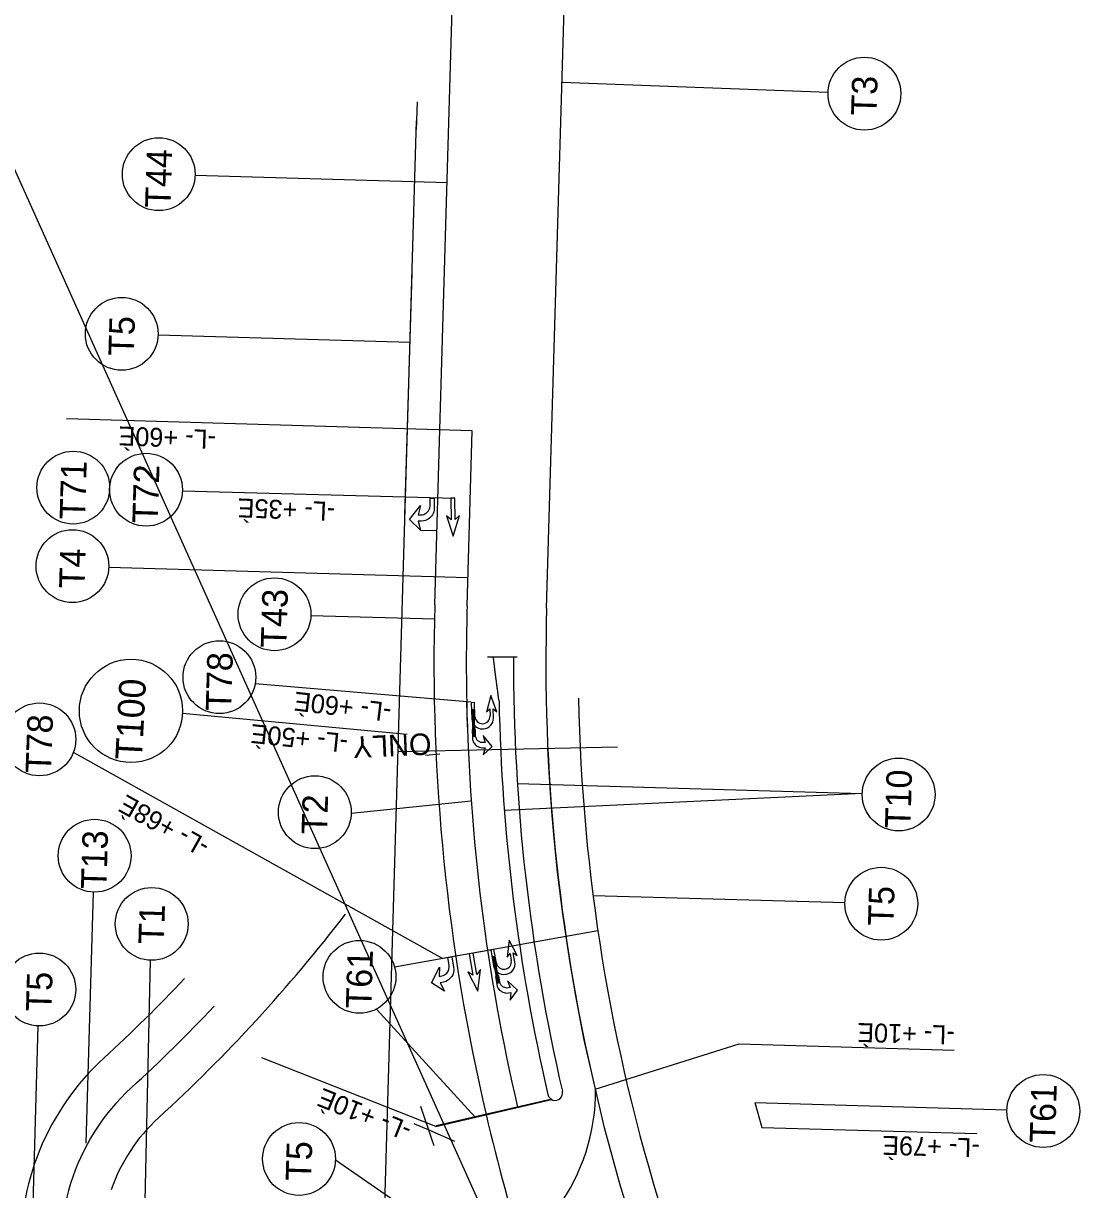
# Model space of a CAD drawing. Extents: x 1657109 to 2100937, y 684916 to 883211.
# Drawn here: x 2097527.1 to 2097918.8, y 685898 to 686330.3 of the extents above; entities that cross this region are included whole.
import ezdxf

# ---------------------------------------------------------------- set-up
doc = ezdxf.new("R2010")
doc.units = 0
for name, color, linetype in [('Prop CMT Detour Removal', 7, 'Continuous'), ('Prop CMT Pvmt Course 1', 7, 'Continuous'), ('Prop CMT Pvmt Gravel', 7, 'Continuous'), ('Prop Conc 1ft 6in Curb and Gutter', 7, 'Continuous'), ('Prop Conc 2ft 6in Curb and Gutter', 7, 'Continuous'), ('Prop Conc Curb 8in x 18in', 7, 'Continuous'), ('Prop Conc Curb and Gutter', 7, 'Continuous'), ('Prop Dimension', 7, 'Continuous'), ('Prop DSN Text', 7, 'Continuous'), ('Prop EOT', 7, 'Continuous'), ('Prop Guardrail Anchor Unit CELL', 7, 'Continuous'), ('Prop Lane Arrow CELL', 7, 'Continuous'), ('Prop Lane Lines', 7, 'Continuous'), ('Prop Paved Shoulder', 7, 'Continuous'), ('Prop Rem of Exist Asph Pvmt', 7, 'Continuous'), ('Prop Sign E Chevron Right', 7, 'Continuous'), ('Scratch_Level_1', 7, 'Continuous'), ('Scratch_Level_3', 7, 'Continuous'), ('Scratch_Level_5', 7, 'Continuous'), ('Sign Bubble', 7, 'Continuous')]:
    doc.layers.add(name, color=color, linetype=linetype)

msp = doc.modelspace()

# ---------------------------------------------------------------- linework, layer by layer
at = {"layer": 'Prop CMT Detour Removal'}
msp.add_line((2097679.67, 686114.82), (2097681.55, 686179.67), dxfattribs=at)
msp.add_arc((2098415.1, 686093.44), 735.75, 178.33483, 193.16901, dxfattribs=at)
at = {"layer": 'Prop CMT Pvmt Course 1'}
for p, q in [((2097700.5, 686081.18), (2097698.81, 686075)), ((2097702.62, 686075.13), (2097700.5, 686081.18)), ((2097694.37, 686078.56), (2097693.17, 686078.51)), ((2097693.17, 686078.51), (2097693.38, 686072.5)), ((2097694.55, 686073.44), (2097694.37, 686078.56)), ((2097698.81, 686075), (2097700.07, 686076.24)), ((2097700.07, 686076.24), (2097700.17, 686073.64)), ((2097701.4, 686072.78), (2097701.28, 686076.29)), ((2097701.28, 686076.29), (2097702.62, 686075.13)), ((2097697.33, 686068.82), (2097697.72, 686068.83)), ((2097707.3, 685990.52), (2097706.5, 685984.16)), ((2097710.25, 685984.83), (2097707.3, 685990.52)), ((2097701.6, 685987.06), (2097700.41, 685986.85)), ((2097700.41, 685986.85), (2097701.47, 685980.92)), ((2097702.5, 685982.02), (2097701.6, 685987.06)), ((2097709.37, 685982.33), (2097708.76, 685985.79)), ((2097708.76, 685985.79), (2097710.25, 685984.83)), ((2097706.5, 685984.16), (2097707.57, 685985.58)), ((2097707.57, 685985.58), (2097708.03, 685983.01)), ((2097705.9, 685977.84), (2097706.29, 685977.91))]:
    msp.add_line(p, q, dxfattribs=at)
for centre, radius, start, end in [((2097697.19, 686072.63), 3.82, 182.0041, 272.0041), ((2097697.36, 686073.54), 2.81, 182.0041, 272.0041), ((2097697.36, 686073.54), 2.81, 272.0041, 2.0041), ((2097697.59, 686072.65), 3.82, 272.0041, 2.0041), ((2097705.26, 685982.52), 2.81, 190.1217, 280.1217), ((2097705.26, 685982.52), 2.81, 280.1217, 10.1217), ((2097705.61, 685981.66), 3.82, 280.1217, 10.1217), ((2097705.23, 685981.59), 3.82, 190.1217, 280.1217)]:
    msp.add_arc(centre, radius, start, end, dxfattribs=at)
at = {"layer": 'Prop CMT Pvmt Gravel'}
for p, q in [((2097825.48, 686304.65), (2097726.81, 686308.43)), ((2097590.82, 686274.01), (2097684.21, 686271.29)), ((2097577.09, 686214.84), (2097670.49, 686212.13)), ((2097693.55, 686179.33), (2097543.06, 686183.7)), ((2097586.09, 686157.06), (2097687.16, 686154.36)), ((2097558.8, 686128.74), (2097691.96, 686124.87)), ((2097633.72, 686110.89), (2097679.53, 686109.56)), ((2097693.16, 686078.66), (2097613.09, 686085.53)), ((2097586.13, 686074.67), (2097669.4, 686066.87)), ((2097710.28, 686048.58), (2097838.17, 686044.86)), ((2097648.7, 686037.52), (2097693.17, 686042.2)), ((2097838.17, 686044.86), (2097705.47, 686038.57)), ((2097550.44, 685915.28), (2097553.14, 686008.3)), ((2097738.34, 686007.11), (2097831.74, 686004.4)), ((2097571.62, 685867.71), (2097574.3, 685983.02)), ((2097694.69, 685924.88), (2097658.05, 685964.97)), ((2097529.26, 685842.85), (2097532.63, 685958.71)), ((2097739.11, 685935.27), (2097792.55, 685952.06)), ((2097792.55, 685952.06), (2097872.25, 685949.75)), ((2097680.01, 685921.44), (2097615.5, 685946.84)), ((2097798.4, 685930.28), (2097891.8, 685927.56)), ((2097800.96, 685921.11), (2097880.66, 685918.8)), ((2097642.82, 685909.02), (2097700.19, 685869.55))]:
    msp.add_line(p, q, dxfattribs=at)
msp.add_lwpolyline([(2097701.6, 685987.06), (2097693.9, 685985.69), (2097682.52, 685983.66), (2097545.68, 686060.1)], dxfattribs=at)
for centre, radius in [((2097838.98, 686304.26), 13.5), ((2097577.32, 686274.4), 13.5), ((2097563.6, 686215.23), 13.5), ((2097545.61, 686158.24), 13.5), ((2097572.6, 686157.45), 13.5), ((2097545.31, 686129.14), 13.5), ((2097620.22, 686111.28), 13.5), ((2097599.81, 686087.96), 13.5), ((2097567.01, 686075.48), 19.14), ((2097533.07, 686064.92), 13.5), ((2097851.66, 686044.47), 13.5), ((2097635.2, 686037.92), 13.5), ((2097553.53, 686021.8), 13.5), ((2097845.23, 686004.01), 13.5), ((2097574.7, 685996.52), 13.5), ((2097651.75, 685976.91), 13.5), ((2097533.02, 685972.21), 13.5), ((2097905.29, 685927.17), 13.5), ((2097629.33, 685909.41), 13.5)]:
    msp.add_circle(centre, radius, dxfattribs=at)
at = {"layer": 'Prop Conc 1ft 6in Curb and Gutter'}
msp.add_arc((2098415.1, 686093.44), 723.75, 181.14892, 193.16901, dxfattribs=at)
at = {"layer": 'Prop Conc 2ft 6in Curb and Gutter'}
msp.add_line((2097691.66, 686114.47), (2097693.55, 686179.33), dxfattribs=at)
for centre, radius, start, end in [((2098415.1, 686093.44), 723.75, 178.33483, 181.14892), ((2097665.53, 685934.68), 73.78, 287.7359, 0.5072)]:
    msp.add_arc(centre, radius, start, end, dxfattribs=at)
at = {"layer": 'Prop Conc Curb 8in x 18in'}
msp.add_lwpolyline([(2097710.24, 686095.39), (2097702.15, 686095.41), (2097699.19, 686095.42)], dxfattribs=at)
at = {"layer": 'Prop Conc Curb and Gutter'}
for centre, radius, start, end in [((2098415.1, 686093.44), 706.25, 179.84144, 193.00645), ((2098415.1, 686093.44), 711.75, 181.14892, 193.00593), ((2097724.29, 685933.87), 2.75, 192.8717, 13.0065)]:
    msp.add_arc(centre, radius, start, end, dxfattribs=at)
msp.add_spline([(2097703.5, 686079.17), (2097703.4, 686079.84), (2097703.31, 686080.51), (2097703.22, 686081.18), (2097703.12, 686081.85), (2097703.03, 686082.52), (2097702.94, 686083.2), (2097702.85, 686083.87), (2097702.76, 686084.54), (2097702.67, 686085.21), (2097702.58, 686085.88), (2097702.5, 686086.56), (2097702.41, 686087.23), (2097702.32, 686087.9), (2097702.24, 686088.58), (2097702.15, 686089.25), (2097702.07, 686089.92), (2097701.98, 686090.6), (2097701.9, 686091.27), (2097701.82, 686091.94), (2097701.73, 686092.62), (2097701.65, 686093.29), (2097701.57, 686093.97), (2097701.49, 686094.64), (2097701.41, 686095.31), (2097701.4, 686095.41)], degree=3, dxfattribs=at)
at = {"layer": 'Prop Dimension'}
for p, q in [((2097674.42, 686142.42), (2097680.47, 686142.33)), ((2097691.75, 686069.43), (2097691.5, 686078.93)), ((2097676.17, 686059.12), (2097681.48, 686059.58)), ((2097740.15, 685993.94), (2097664.77, 685980.49))]:
    msp.add_line(p, q, dxfattribs=at)
at = {"layer": 'Prop DSN Text'}
for points in [[(2097679.45, 685914.25), (2097678.59, 685916.78), (2097674.46, 685928.78)], [(2097671.93, 685922.56), (2097677.42, 685920.16), (2097686.96, 685915.99)]]:
    msp.add_lwpolyline(points, dxfattribs=at)
at = {"layer": 'Prop EOT'}
msp.add_line((2097721.15, 686113.61), (2097743.93, 686897.18), dxfattribs=at)
msp.add_arc((2098415.1, 686093.44), 694.25, 178.33483, 193.16901, dxfattribs=at)
at = {"layer": 'Prop Guardrail Anchor Unit CELL'}
for centre, radius, start, end in [((2097180.74, 686358.34), 587.6, 312.43424, 322.438), ((2097180.74, 686358.34), 557.6, 312.4342, 316.7547), ((2097621.08, 685876.69), 95, 132.4342, 183.1561), ((2097621.08, 685876.69), 65, 132.4342, 160.85)]:
    msp.add_arc(centre, radius, start, end, dxfattribs=at)
at = {"layer": 'Prop Lane Arrow CELL'}
msp.add_line((2097668.62, 686148), (2097671.24, 686237.8), dxfattribs=at)
for radius, start, end in [(682.25, 181.10817, 197.44435), (735.75, 193.16901, 201.91468)]:
    msp.add_arc((2098415.1, 686093.44), radius, start, end, dxfattribs=at)
at = {"layer": 'Prop Lane Lines'}
for p, q in [((2097680.02, 685921.45), (2097722.93, 685931.49)), ((2097798.4, 685930.28), (2097800.96, 685921.11))]:
    msp.add_line(p, q, dxfattribs=at)
at = {"layer": 'Prop Paved Shoulder'}
for points in [[(2097694.73, 686068.6), (2097693.54, 686068.57), (2097693.62, 686065.49), (2097693.66, 686064.93), (2097693.75, 686064.5), (2097693.91, 686064.03), (2097694.12, 686063.65), (2097694.34, 686063.35), (2097694.69, 686062.97), (2097694.99, 686062.71), (2097695.35, 686062.44), (2097695.83, 686062.17), (2097696.21, 686062.03), (2097696.72, 686061.9), (2097697.41, 686061.82), (2097698.37, 686061.84), (2097697.64, 686059.15), (2097700.93, 686062.31), (2097697.66, 686066.39), (2097698.32, 686063.73), (2097697.53, 686063.71), (2097697.08, 686063.72), (2097696.67, 686063.82), (2097696.35, 686063.97), (2097695.93, 686064.2), (2097695.64, 686064.42), (2097695.31, 686064.8), (2097695.08, 686065.24), (2097694.9, 686065.69), (2097694.78, 686066.32)], [(2097694.73, 686068.59), (2097693.54, 686068.56), (2097693.61, 686065.49), (2097693.66, 686064.93), (2097693.75, 686064.5), (2097693.91, 686064.03), (2097694.12, 686063.64), (2097694.34, 686063.35), (2097694.68, 686062.97), (2097694.99, 686062.71), (2097695.35, 686062.44), (2097695.83, 686062.17), (2097696.21, 686062.03), (2097696.72, 686061.89), (2097697.41, 686061.82), (2097698.37, 686061.84), (2097697.64, 686059.15), (2097700.93, 686062.31), (2097697.66, 686066.39), (2097698.32, 686063.73), (2097697.53, 686063.71), (2097697.08, 686063.72), (2097696.67, 686063.82), (2097696.34, 686063.96), (2097695.93, 686064.2), (2097695.64, 686064.41), (2097695.31, 686064.8), (2097695.08, 686065.24), (2097694.9, 686065.69), (2097694.78, 686066.32)], [(2097703.36, 685977.25), (2097702.18, 685977.05), (2097702.69, 685974.02), (2097702.82, 685973.47), (2097702.96, 685973.06), (2097703.19, 685972.62), (2097703.46, 685972.26), (2097703.71, 685972), (2097704.11, 685971.67), (2097704.45, 685971.46), (2097704.85, 685971.25), (2097705.35, 685971.05), (2097705.75, 685970.96), (2097706.27, 685970.9), (2097706.97, 685970.92), (2097707.91, 685971.08), (2097707.58, 685968.31), (2097710.39, 685971.9), (2097706.57, 685975.48), (2097707.6, 685972.94), (2097706.82, 685972.81), (2097706.38, 685972.76), (2097705.95, 685972.8), (2097705.61, 685972.89), (2097705.17, 685973.07), (2097704.85, 685973.24), (2097704.47, 685973.58), (2097704.18, 685973.98), (2097703.93, 685974.4), (2097703.73, 685975)], [(2097703.36, 685977.25), (2097702.18, 685977.05), (2097702.69, 685974.02), (2097702.82, 685973.47), (2097702.96, 685973.06), (2097703.19, 685972.62), (2097703.46, 685972.27), (2097703.71, 685972), (2097704.11, 685971.67), (2097704.45, 685971.46), (2097704.85, 685971.25), (2097705.36, 685971.05), (2097705.75, 685970.96), (2097706.27, 685970.9), (2097706.97, 685970.92), (2097707.91, 685971.08), (2097707.58, 685968.31), (2097710.39, 685971.9), (2097706.57, 685975.48), (2097707.6, 685972.94), (2097706.82, 685972.81), (2097706.38, 685972.76), (2097705.95, 685972.8), (2097705.61, 685972.9), (2097705.17, 685973.07), (2097704.85, 685973.24), (2097704.47, 685973.58), (2097704.18, 685973.98), (2097703.94, 685974.4), (2097703.74, 685975)]]:
    msp.add_lwpolyline(points, close=True, dxfattribs=at)
at = {"layer": 'Prop Rem of Exist Asph Pvmt'}
msp.add_line((2097681.55, 686179.67), (2097694.41, 686621.93), dxfattribs=at)
at = {"layer": 'Prop Sign E Chevron Right'}
for p, q in [((2097817.26, 685624.22), (2097510.8, 686305.14)), ((2097673.08, 686301.29), (2097672.78, 686290.92)), ((2097653.39, 685623.98), (2097672.88, 686294.24)), ((2097666.08, 686060.46), (2097747.39, 686062.16))]:
    msp.add_line(p, q, dxfattribs=at)
msp.add_lwpolyline([(2097774.95, 685824.77), (2097768.11, 685841.69), (2097763.2, 685854.69), (2097761, 685860.78), (2097758.45, 685868.09), (2097755.26, 685877.58), (2097748.31, 685900.14), (2097742.63, 685920.91), (2097734.98, 685954.09), (2097731.95, 685969.82), (2097729.85, 685982.04), (2097728.33, 685991.83), (2097727.13, 686000.31), (2097725.21, 686015.75), (2097723.9, 686028.46), (2097723.18, 686036.72), (2097722.54, 686045.08), (2097721.93, 686054.74), (2097721.58, 686061.62)], dxfattribs=at)
at = {"layer": 'Scratch_Level_1'}
for centre, radius, start, end in [((2097180.74, 686358.34), 572.6, 312.4342, 316.7547), ((2097621.08, 685876.69), 80, 132.4342, 193.3081)]:
    msp.add_arc(centre, radius, start, end, dxfattribs=at)
at = {"layer": 'Scratch_Level_3'}
for points in [[(2097677.99, 686154.37), (2097679.49, 686154.34), (2097679.43, 686150.47), (2097679.38, 686149.75), (2097679.27, 686149.21), (2097679.07, 686148.63), (2097678.81, 686148.13), (2097678.54, 686147.76), (2097678.11, 686147.27), (2097677.72, 686146.95), (2097677.27, 686146.6), (2097676.67, 686146.26), (2097676.2, 686146.07), (2097675.56, 686145.9), (2097674.68, 686145.79), (2097673.48, 686145.81), (2097674.42, 686142.42), (2097670.23, 686146.37), (2097674.32, 686151.55), (2097673.51, 686148.19), (2097674.51, 686148.17), (2097675.08, 686148.19), (2097675.6, 686148.33), (2097676, 686148.51), (2097676.53, 686148.81), (2097676.89, 686149.09), (2097677.29, 686149.58), (2097677.59, 686150.14), (2097677.81, 686150.7), (2097677.94, 686151.49)], [(2097677.99, 686154.37), (2097679.49, 686154.34), (2097679.43, 686150.47), (2097679.38, 686149.75), (2097679.27, 686149.21), (2097679.07, 686148.63), (2097678.81, 686148.13), (2097678.54, 686147.76), (2097678.11, 686147.27), (2097677.72, 686146.95), (2097677.27, 686146.6), (2097676.67, 686146.26), (2097676.2, 686146.07), (2097675.56, 686145.9), (2097674.68, 686145.79), (2097673.48, 686145.81), (2097674.42, 686142.42), (2097670.23, 686146.37), (2097674.32, 686151.55), (2097673.51, 686148.19), (2097674.51, 686148.17), (2097675.08, 686148.19), (2097675.6, 686148.33), (2097676, 686148.51), (2097676.53, 686148.81), (2097676.89, 686149.09), (2097677.29, 686149.58), (2097677.59, 686150.14), (2097677.81, 686150.7), (2097677.94, 686151.49)], [(2097684.49, 685984.01), (2097685.96, 685984.27), (2097686.65, 685980.46), (2097686.73, 685979.74), (2097686.74, 685979.19), (2097686.65, 685978.58), (2097686.49, 685978.04), (2097686.3, 685977.63), (2097685.96, 685977.06), (2097685.65, 685976.67), (2097685.27, 685976.24), (2097684.75, 685975.79), (2097684.32, 685975.52), (2097683.72, 685975.22), (2097682.89, 685974.95), (2097681.7, 685974.74), (2097683.27, 685971.6), (2097678.41, 685974.67), (2097681.42, 685980.54), (2097681.28, 685977.08), (2097682.26, 685977.26), (2097682.81, 685977.39), (2097683.3, 685977.62), (2097683.66, 685977.88), (2097684.12, 685978.27), (2097684.42, 685978.61), (2097684.72, 685979.17), (2097684.9, 685979.78), (2097685.01, 685980.37), (2097684.99, 685981.18)], [(2097684.49, 685984.01), (2097685.96, 685984.27), (2097686.65, 685980.46), (2097686.73, 685979.74), (2097686.74, 685979.19), (2097686.65, 685978.58), (2097686.49, 685978.04), (2097686.3, 685977.63), (2097685.96, 685977.06), (2097685.65, 685976.67), (2097685.27, 685976.24), (2097684.75, 685975.79), (2097684.32, 685975.52), (2097683.72, 685975.22), (2097682.89, 685974.95), (2097681.7, 685974.74), (2097683.27, 685971.6), (2097678.41, 685974.67), (2097681.42, 685980.54), (2097681.28, 685977.08), (2097682.26, 685977.26), (2097682.81, 685977.39), (2097683.3, 685977.62), (2097683.66, 685977.88), (2097684.12, 685978.27), (2097684.42, 685978.61), (2097684.72, 685979.17), (2097684.9, 685979.78), (2097685.01, 685980.37), (2097684.99, 685981.18)]]:
    msp.add_lwpolyline(points, close=True, dxfattribs=at)
at = {"layer": 'Scratch_Level_5'}
for points in [[(2097688.81, 686147.87), (2097687.2, 686146.36), (2097687.16, 686154.36), (2097685.66, 686154.35), (2097685.7, 686146.35), (2097684.06, 686147.84), (2097686.48, 686140.23)], [(2097688.81, 686147.87), (2097687.2, 686146.36), (2097687.16, 686154.36), (2097685.66, 686154.35), (2097685.7, 686146.35), (2097684.06, 686147.84), (2097686.48, 686140.23)], [(2097696.64, 685979.57), (2097695.31, 685977.81), (2097693.9, 685985.69), (2097692.42, 685985.42), (2097693.83, 685977.55), (2097691.97, 685978.74), (2097695.64, 685971.65)], [(2097696.64, 685979.57), (2097695.31, 685977.81), (2097693.9, 685985.69), (2097692.42, 685985.42), (2097693.83, 685977.55), (2097691.97, 685978.74), (2097695.64, 685971.65)]]:
    msp.add_lwpolyline(points, close=True, dxfattribs=at)
at = {"layer": 'Sign Bubble'}
msp.add_line((2097723.13, 685931.55), (2097680.18, 685921.62), dxfattribs=at)

# ---------------------------------------------------------------- texts
at = {"layer": 'Prop CMT Pvmt Course 1'}
for rotation, p in [(2.0041, (2097692.75, 686065.77)), (10.1217, (2097701.8, 685974.17))]:
    msp.add_text('l', height=9.82, rotation=rotation, dxfattribs=at).set_placement(p)
at = {"layer": 'Prop CMT Pvmt Gravel'}
for s, height, rotation, p in [('T3', 9.45, 88.3348, (2097843.46, 686296.01)), ('T44', 9.45, 88.3348, (2097581.68, 686261.81)), ('T5', 9.45, 88.3348, (2097568.08, 686206.94)), ('-L- +60È', 7, 177.8037, (2097598.66, 686179.54)), ('T71', 9.45, 88.3348, (2097549.99, 686146.35)), ('T72', 9.45, 88.3348, (2097576.96, 686144.89)), ('-L- +35È', 7, 177.8037, (2097642.85, 686152.86)), ('T4', 9.45, 88.3348, (2097549.79, 686120.79)), ('T43', 9.45, 88.3348, (2097624.58, 686098.78)), ('T78', 9.45, 88.3348, (2097604.17, 686075.32)), ('T100', 9.875, 86.9833, (2097571.05, 686057.11)), ('-L- +60È', 7, 173.1474, (2097663.88, 686078.31)), ('T78', 9.45, 87.8906, (2097537.34, 686052.26)), ('-L- +50È', 7, 173.9934, (2097647.76, 686066.84)), ('ONLY', 8, 182.638, (2097678.22, 686067.28)), ('T10', 9.45, 88.3348, (2097856.02, 686031.83)), ('-L- +68È', 7, 150.8094, (2097596.78, 686027.11)), ('T2', 9.45, 88.3348, (2097639.69, 686029.61)), ('T13', 9.45, 88.3348, (2097557.9, 686009.3)), ('T5', 9.45, 88.3348, (2097849.72, 685995.71)), ('T1', 9.45, 88.3348, (2097579.2, 685988.88)), ('T61', 9.45, 88.3348, (2097656.13, 685965.02)), ('T5', 9.45, 88.3348, (2097537.51, 685963.91)), ('-L- +10È', 7, 178.4251, (2097872.56, 685958.8)), ('-L- +10È', 7, 158.1638, (2097671.65, 685922.4)), ('T61', 9.45, 88.3348, (2097909.68, 685915.29)), ('-L- +79È', 7, 178.4251, (2097881.83, 685916.97)), ('T5', 9.45, 88.3348, (2097633.81, 685901.12))]:
    msp.add_text(s, height=height, rotation=rotation, dxfattribs=at).set_placement(p)

doc.saveas('drawing.dxf')
